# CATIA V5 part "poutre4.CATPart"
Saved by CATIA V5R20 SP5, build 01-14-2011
Part number: poutre4
Bounding box of the stored display mesh (mm): x 250 to 350, y 300.933 to 1600.186, z 549.997 to 978.435
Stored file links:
  F:\iao fini\poutre4.CATPart
  F:\iao fini\iao-finipbgliss.CATProduct
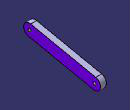
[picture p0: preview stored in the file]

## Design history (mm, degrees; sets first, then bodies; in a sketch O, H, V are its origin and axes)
External parameters (linked from other documents)
  External.rayontrou = 50 mm
  External.epaisseur = 50 mm
Set1
  Plane1 "Plan4": linked copy from another document
  Point1: linked copy from another document
  Point2: linked copy from another document
Body1 (main body)
  Sketch1 on Plane1, origin (300, 0, 0), H (0, 1, 0), V (0, 0, 1)
    circle A1 centre (1500.1993, 649.9838) radius 25
    point P1 (1500.1993, 649.9838)
    circle A2 centre (400.9199, 878.4484) radius 25
    point P2 (400.9199, 878.4484)
    reference projected point E1 (1500.1993, 649.9838) from Point1
    reference projected point E2 (400.9199, 878.4484) from Point2
    arc A3 centre (1500.1993, 649.9838) radius 100 from (1479.851, 552.0759) to (1520.5476, 747.8916) ccw
    arc A4 centre (400.9199, 878.4484) radius 100 from (421.2682, 976.3563) to (380.5716, 780.5406) ccw
    line L1 (421.2682, 976.3563) -> (1520.5476, 747.8916)
    line L2 (1479.851, 552.0759) -> (380.5716, 780.5406)
    radius A2 = 25 {= 1/2*External.rayontrou}
    radius A1 = 25 {= 1/2*External.rayontrou}
    radius A3 = 100 {= 2*External.rayontrou}
    radius A4 = 100 {= External.rayontrou *2}
    coincidence: E1 P1, P2 E2
    concentricity: A3 A1, A4 A2
    tangency: L1 A3, L2 A4, A3 L2, L1 A4
  Pad1: profile Sketch1, direction (1, 0, 0), length 50 {= External.epaisseur}, mirrored extent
